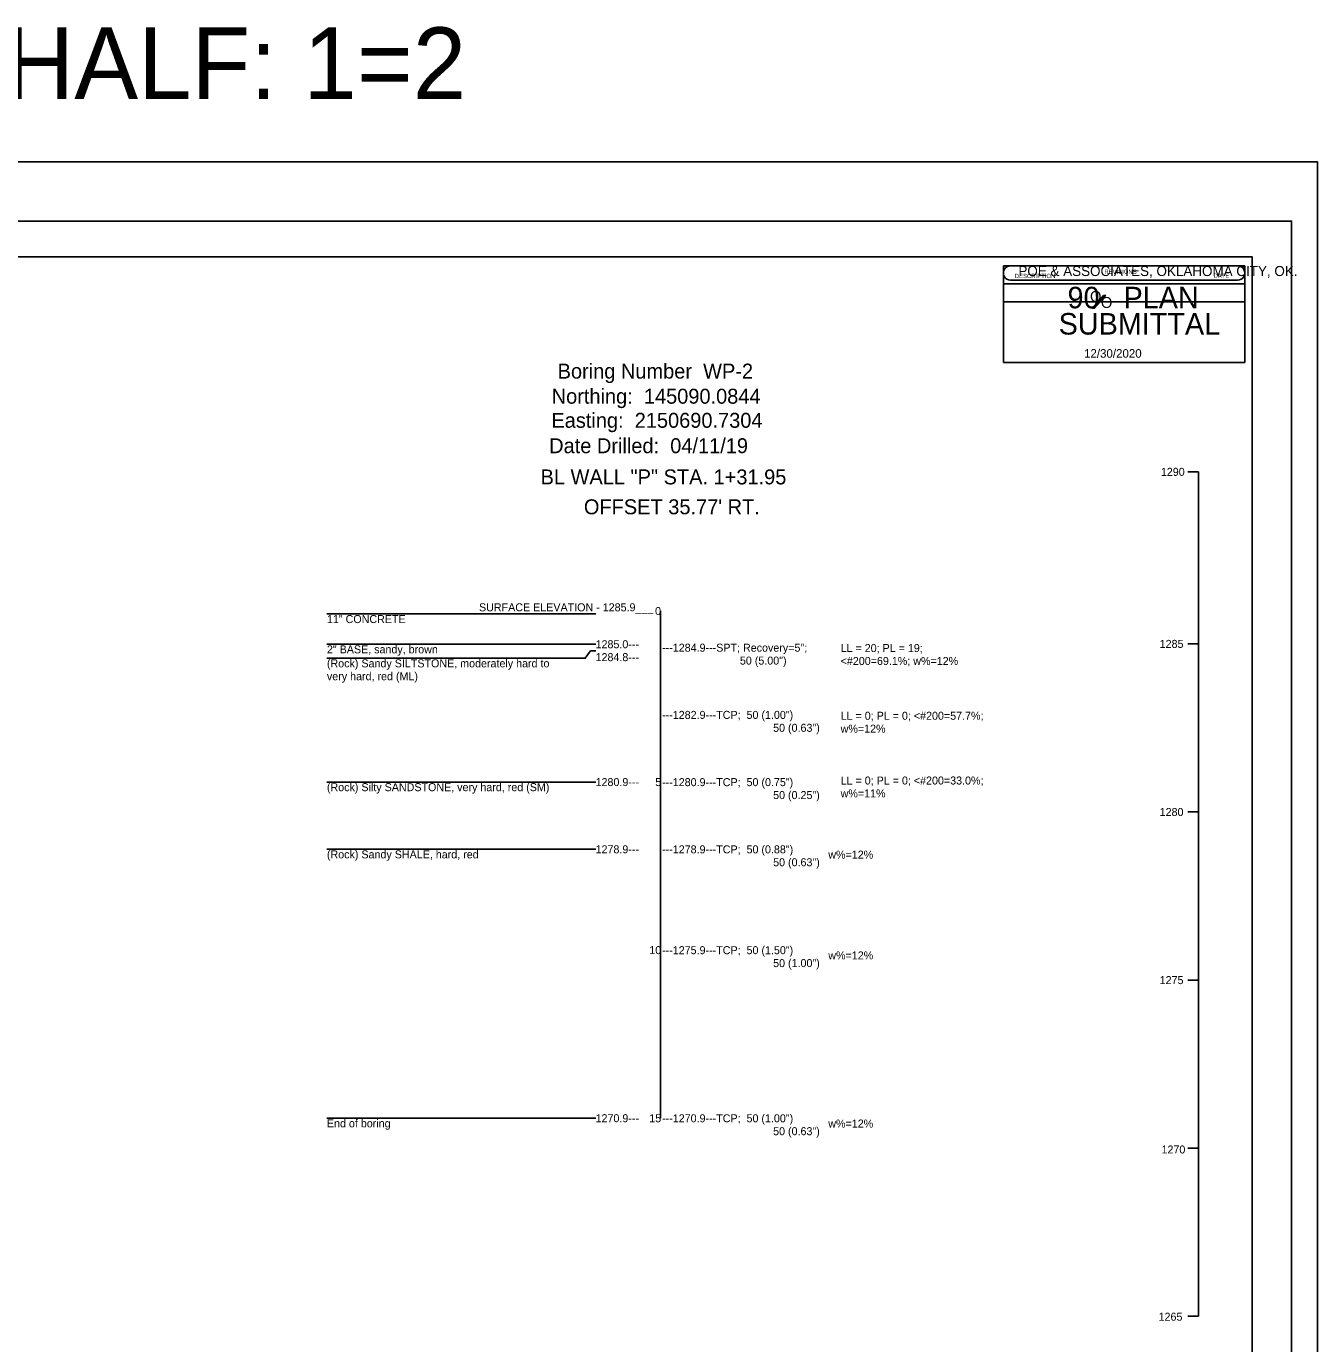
# Model space of a CAD drawing. Extents: x 6.6 to 42.6, y 24.1 to 55.9.
# Drawn here: x 24.62 to 42.62, y 37.49 to 55.86 of the extents above; entities that cross this region are included whole.
import ezdxf

# ---------------------------------------------------------------- set-up
doc = ezdxf.new("R2010")
doc.units = 0
for name, color, linetype in [('S', 7, 'Continuous'), ('SHT_Plot_Shape_Full', 7, 'Continuous'), ('SHT_Plot_Shape_Half', 7, 'Continuous'), ('SHT_Sheet_Border', 7, 'Continuous'), ('SHT_Stamp_90_Submit', 7, 'Continuous'), ('SHT_Stamp_Rev_Block', 7, 'Continuous')]:
    doc.layers.add(name, color=color, linetype=linetype)

msp = doc.modelspace()

# ---------------------------------------------------------------- linework, layer by layer
msp.add_line((40.965, 37.876), (40.965, 49.648))
for points in [[(40.815, 49.648), (40.965, 49.648)], [(28.814, 47.668), (32.564, 47.668)], [(33.462, 47.713), (33.462, 40.637)], [(28.814, 47.246), (32.564, 47.246)], [(40.815, 47.251), (40.965, 47.251)], [(28.814, 47.051), (32.414, 47.051), (32.489, 47.152), (32.564, 47.152)], [(28.814, 45.324), (32.564, 45.324)], [(40.815, 44.907), (40.965, 44.907)], [(28.814, 44.387), (32.564, 44.387)], [(40.815, 42.563), (40.965, 42.563)], [(28.814, 40.637), (32.564, 40.637)], [(40.815, 40.219), (40.965, 40.219)], [(40.815, 37.876), (40.965, 37.876)]]:
    msp.add_lwpolyline(points)
at = {"layer": 'SHT_Plot_Shape_Full'}
msp.add_lwpolyline([(6.624, 53.971), (42.624, 53.971), (42.624, 29.971), (6.624, 29.971)], close=True, dxfattribs=at)
at = {"layer": 'SHT_Plot_Shape_Half'}
msp.add_lwpolyline([(8.262, 53.146), (42.262, 53.146), (42.262, 31.146), (8.262, 31.146)], close=True, dxfattribs=at)
at = {"layer": 'SHT_Sheet_Border'}
msp.add_lwpolyline([(10.212, 52.646), (41.712, 52.646), (41.712, 31.646), (10.212, 31.646)], close=True, dxfattribs=at)
at = {"layer": 'SHT_Stamp_90_Submit'}
for p, q in [((38.343, 52.522), (41.509, 52.522)), ((38.243, 52.272), (41.609, 52.272)), ((38.243, 51.173), (38.243, 52.272)), ((38.343, 52.322), (41.509, 52.322)), ((41.609, 51.173), (41.609, 52.272)), ((39.486, 51.934), (39.641, 52.107)), ((39.504, 51.934), (39.659, 52.107)), ((39.509, 51.934), (39.664, 52.107)), ((39.516, 51.934), (39.672, 52.107)), ((39.641, 52.107), (39.672, 52.107)), ((39.486, 51.934), (39.516, 51.934)), ((38.243, 51.173), (41.609, 51.173))]:
    msp.add_line(p, q, dxfattribs=at)
for centre, start, end in [((38.343, 52.422), 89.9952, 270), ((41.509, 52.422), 270, 90.0048)]:
    msp.add_arc(centre, 0.1, start, end, dxfattribs=at)
at = {"layer": 'SHT_Stamp_Rev_Block'}
for p, q in [((38.243, 52.522), (38.243, 52.022)), ((41.609, 52.522), (38.243, 52.522)), ((41.609, 52.022), (41.609, 52.522)), ((41.609, 52.272), (38.243, 52.272)), ((41.609, 52.022), (38.243, 52.022))]:
    msp.add_line(p, q, dxfattribs=at)

# ---------------------------------------------------------------- texts
for s, height, p in [('Boring Number  WP-2', 0.2083, (32.03, 50.95)), ('Northing:  145090.0844', 0.20832, (31.947, 50.6)), ('Easting:  2150690.7304', 0.20832, (31.943, 50.264)), ('Date Drilled:  04/11/19', 0.20832, (31.912, 49.91)), ('BL WALL "P" STA. 1+31.95', 0.20832, (31.792, 49.475)), ('1290', 0.1116, (40.439, 49.594)), ("OFFSET 35.77' RT.", 0.20832, (32.396, 49.058)), ('SURFACE ELEVATION - 1285.9___', 0.1116, (30.934, 47.705)), ('0', 0.112, (33.388, 47.653)), ('11" CONCRETE', 0.1116, (28.814, 47.541)), ('2" BASE, sandy, brown', 0.1116, (28.814, 47.119)), ('1285.0---', 0.1116, (32.559, 47.19)), ('---1284.9---SPT; Recovery=5";', 0.1116, (33.486, 47.142)), ('LL = 20; PL = 19;', 0.1116, (35.975, 47.137)), ('1285', 0.1116, (40.422, 47.195)), ('(Rock) Sandy SILTSTONE, moderately hard to', 0.1116, (28.814, 46.924)), ('1284.8---', 0.1116, (32.559, 47.01)), ('50 (5.00")', 0.1116, (34.571, 46.962)), ('<#200=69.1%; w%=12%', 0.1116, (35.975, 46.957)), ('very hard, red (ML)', 0.1116, (28.814, 46.744)), ('---1282.9---TCP;  50 (1.00")', 0.1116, (33.486, 46.205)), ('LL = 0; PL = 0; <#200=57.7%;', 0.1116, (35.975, 46.193)), ('50 (0.63")', 0.1116, (35.034, 46.025)), ('w%=12%', 0.1116, (35.975, 46.013)), ('1280.9---', 0.1116, (32.559, 45.268)), ('5', 0.112, (33.391, 45.268)), ('---1280.9---TCP;  50 (0.75")', 0.1116, (33.486, 45.267)), ('LL = 0; PL = 0; <#200=33.0%;', 0.1116, (35.975, 45.29)), ('(Rock) Silty SANDSTONE, very hard, red (SM)', 0.1116, (28.814, 45.197)), ('50 (0.25")', 0.1116, (35.034, 45.087)), ('w%=11%', 0.1116, (35.975, 45.11)), ('1280', 0.1116, (40.422, 44.851)), ('(Rock) Sandy SHALE, hard, red', 0.1116, (28.814, 44.26)), ('1278.9---', 0.1116, (32.559, 44.331)), ('---1278.9---TCP;  50 (0.88")', 0.1116, (33.486, 44.33)), ('50 (0.63")', 0.1116, (35.034, 44.15)), ('w%=12%', 0.1116, (35.803, 44.257)), ('10', 0.1116, (33.308, 42.925)), ('---1275.9---TCP;  50 (1.50")', 0.1116, (33.486, 42.924)), ('50 (1.00")', 0.1116, (35.034, 42.744)), ('w%=12%', 0.1116, (35.803, 42.851)), ('1275', 0.1116, (40.422, 42.507)), ('End of boring', 0.1116, (28.814, 40.51)), ('1270.9---', 0.1116, (32.559, 40.581)), ('15', 0.1116, (33.308, 40.581)), ('---1270.9---TCP;  50 (1.00")', 0.1116, (33.486, 40.58)), ('w%=12%', 0.1116, (35.803, 40.507)), ('50 (0.63")', 0.1116, (35.034, 40.4)), ('1270', 0.1116, (40.448, 40.145)), ('1265', 0.1116, (40.407, 37.813))]:
    msp.add_text(s, height=height).set_placement(p)
at = {"layer": 'S'}
msp.add_text('FULL: 1=1   HALF: 1=2', height=1, dxfattribs=at).set_placement((16.93, 54.847))
at = {"layer": 'SHT_Stamp_90_Submit'}
for s, height, p in [('POE & ASSOCIATES, OKLAHOMA CITY, OK.', 0.14, (38.453, 52.38)), ('90   PLAN', 0.3, (39.138, 51.93)), ('O', 0.153, (39.451, 52.019)), ('O', 0.153, (39.603, 51.935)), ('SUBMITTAL', 0.3, (39.014, 51.564)), ('12/30/2020', 0.12, (39.368, 51.241))]:
    msp.add_text(s, height=height, dxfattribs=at).set_placement(p)
at = {"layer": 'SHT_Stamp_Rev_Block'}
for s, height, p in [('DESCRIPTION', 0.05999, (38.403, 52.351)), ('REVISIONS', 0.06, (39.651, 52.41)), ('DATE', 0.06, (41.172, 52.355))]:
    msp.add_text(s, height=height, dxfattribs=at).set_placement(p)

doc.saveas('drawing.dxf')
